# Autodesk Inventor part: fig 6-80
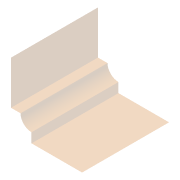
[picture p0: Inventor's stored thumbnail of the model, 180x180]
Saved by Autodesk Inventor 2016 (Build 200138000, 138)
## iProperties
Shininess: 64.0
Length Units: 11269
Angle Units: 11279
Time Units: 11290
Mass Units: 11283
Length Display Precision: 3
Angle Display Precision: 2
Compacted: True
Part Number: fig 6-80
Document SubType Name: Modeling
Created: 2003-10
Designer: Owner
Manufacturer: Standard
Standards Organization: Custom
Density: 1 g/cm^3
Material: Generic
Appearance: Default
Density: 0.0
Volumn: 0.0
Area: 0.0
PropertySet Name: Model Information
Control State: 0
Master: False
Checked Out: False
Author: Owner
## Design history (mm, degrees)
node "Sketch1"
sketch "Sketch2"
  geometry: L1 (22.777, 31.862)-(22.777, 0.2); L2 (7.777, -14.8)-(-29.161, -14.8); A1 r 15 centre (7.777, 0.2) between (7.777, -14.8) and (22.777, 0.2)
  constraints: 4 end point, 2 point on circle, 2 tangent, 1 centre point, 1 perpendicular, 1 vertical
  dimensions: "d23" = 15 radius of A1
extrude_surface "ExtrusionSrf1" sketch "Sketch2" dims "d24" = 63.5, "d25" = 0
feature "OffsetSrf12" dims "d31" = 7, "d32" = 1
body "Solid1"
body "Srf1"
